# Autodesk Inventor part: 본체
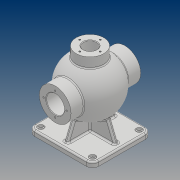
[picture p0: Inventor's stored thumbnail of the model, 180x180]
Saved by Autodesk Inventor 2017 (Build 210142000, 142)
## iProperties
Part Number: 본체
Material: 일반
Document SubType Name: Modeling
Designer: 13
Density: 1 g/cm^3
Appearance: 기본값
Author: 13
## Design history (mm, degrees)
sketch "스케치1"
  geometry: L1 (53, 0)-(-53, 0); A1 r 53 centre (0, 0) between (53, 0) and (-53, 0); 1 further point
  constraints: 2 end point, 2 horizontal alignment, 2 point on circle, 1 centre point, 1 coincident, 1 horizontal
  dimensions: "d1" = 53 radius of A1
revolve "회전1" sketch "스케치1" stored, may be unused: angle "d2" = 90 deg
sketch "스케치2"
  geometry: L1 (43, 0)-(-43, 0); L2 (0, 0)-(-100, 0); A1 r 43 centre (0, 0) between (43, 0) and (-43, 0); 1 further point
  constraints: 4 end point, 2 horizontal alignment, 2 point on circle, 1 centre point, 1 coincident, 1 horizontal, 1 midpoint, 1 point on line
  dimensions: "d3" = 43 radius of A1; "d4" = 100 distance of L2.start L2.end
revolve "회전2" sketch "스케치2" stored, may be unused: angle "d5" = 90 deg
node "작업 평면2"
sketch "스케치3"
  geometry: C1 r 31 at (0, 0); 1 further point
  constraints: 1 centre point, 1 coincident
  dimensions: "d8" = 62 diameter of C1
extrude "돌출1" join sketch "스케치3" stored distance "d9" = 10; taper "d10" = 0 deg
sketch "스케치4"
  geometry: C1 r 17.5 at (0, 0); 1 further point
  constraints: 1 centre point, 1 coincident
  dimensions: "d11" = 35 diameter of C1
extrude "돌출2" cut sketch "스케치4" stored distance "d12" = 10; taper "d13" = 0 deg
node "작업 평면3"
sketch "스케치5"
  geometry: C1 r 27 at (0, 0); 1 further point
  constraints: 1 centre point, 1 coincident
  dimensions: "d15" = 54 diameter of C1
extrude "돌출3" join sketch "스케치5" stored distance "d16" = 10; taper "d17" = 0 deg
sketch "스케치6"
  geometry: C1 r 13 at (0, 0); 1 further point
  constraints: 1 centre point, 1 coincident
  dimensions: "d18" = 26 diameter of C1
extrude "돌출4" cut sketch "스케치6" distance "d19" = 40; taper "d20" = 0 deg
node "작업 평면4"
sketch "스케치7"
  geometry: C1 r 18.5 at (0, 0); 1 further point
  constraints: 1 centre point, 1 coincident
  dimensions: "d22" = 37 diameter of C1
extrude "돌출5" cut sketch "스케치7" distance "d23" = 1.75; taper "d24" = 0 deg
node "작업 평면5"
sketch "스케치8"
  geometry: L1 (-62.5, 57.5)-(62.5, 57.5); L2 (62.5, 57.5)-(62.5, -57.5); L3 (62.5, -57.5)-(-62.5, -57.5); L4 (-62.5, -57.5)-(-62.5, 57.5); L5 (-62.5, 57.5)-(62.5, -57.5); L6 (62.5, 57.5)-(-62.5, -57.5); 1 further point
  constraints: 12 end point, 2 midpoint, 2 parallel, 1 horizontal, 1 perpendicular
  dimensions: "d26" = 115 distance of L1.end L2.end; "d27" = 125 distance of L1.start L1.end
extrude "돌출6" join sketch "스케치8" distance "d28" = 10; taper "d29" = 0 deg
sketch "스케치9"
  geometry: L1 (-4, 4)-(4, 4); L2 (4, 4)-(4, -4); L3 (4, -4)-(-4, -4); L4 (-4, -4)-(-4, 4); L5 (-4, 4)-(4, -4); L6 (4, 4)-(-4, -4); 1 further point
  constraints: 12 end point, 2 midpoint, 2 parallel, 1 horizontal, 1 perpendicular
  dimensions: "d30" = 8 distance of L2.end L3.end; "d31" = 8 distance of L1.end L2.end
extrude "돌출7" join sketch "스케치9" stored distance "d32" = 10; taper "d33" = 0 deg
sketch "스케치10"
  geometry: L1 (52.5, -75)-(39.167, -42); L2 (62.5, -85)-(62.5, -75) reference; L3 (-62.5, -75)-(62.5, -75) reference; 1 further point
  constraints: 2 end point, 1 point on line
  dimensions: "d34" = 10 distance from line of L1.start L2; "d36" = 22 deg angle of L2 L1; "d37" = 33 vertical distance of L1.start L1.end
feature "리브1" sketch "스케치10" dims "d38" = 1, "d39" = 8, "d40" = 0, "d41" = 0, "d42" = 1, "d43" = 1
sketch "스케치11"
  geometry: L1 (-52.5, -75)-(-42.399, -50); L2 (-62.5, -85)-(-62.5, -75) reference; L3 (62.5, -75)-(-62.5, -75) reference; 1 further point
  constraints: 2 end point, 1 point on line
  dimensions: "d44" = 10 distance from line of L2 L1.start; "d45" = 22 deg angle of L2 L1; "d46" = 25 vertical distance of L1.start L1.end
feature "리브2" sketch "스케치11" dims "d47" = 1, "d48" = 8, "d49" = 0, "d50" = 0, "d51" = 1, "d52" = 1
sketch "스케치12"
  geometry: L1 (-47.5, -75)-(-37.399, -50); L2 (-57.5, -85)-(-57.5, -75) reference; L3 (57.5, -75)-(-57.5, -75) reference; 1 further point
  constraints: 2 end point, 1 point on line
  dimensions: "d53" = 10 distance from line of L1.start L2; "d54" = 22 deg angle of L2 L1; "d55" = 25 vertical distance of L1.start L1.end
feature "리브3" sketch "스케치12" dims "d56" = 1, "d57" = 8, "d58" = 0, "d59" = 0, "d60" = 1, "d61" = 1
sketch "스케치13"
  geometry: L1 (47.5, -75)-(37.399, -50); L2 (57.5, -85)-(57.5, -75) reference; L3 (57.5, -75)-(-57.5, -75) reference; 1 further point
  constraints: 2 end point, 1 point on line
  dimensions: "d62" = 10 distance from line of L2 L1.start; "d63" = 22 deg angle of L2 L1; "d64" = 25 vertical distance of L1.start L1.end
feature "리브4" sketch "스케치13" dims "d65" = 1, "d66" = 8, "d67" = 0, "d68" = 0, "d69" = 1, "d70" = 1
fillet "모깎기1" dims "d71" = 12
sketch "스케치15"
  geometry: 2 further points
  constraints: 1 vertical alignment
  dimensions: "d75" = 22.5 distance of point (0, 0) point (0, 22.5)
hole "구멍1" sketch "스케치15" at (0, 22.5) diameter "d76" = 3.242; stored, may be unused: countersink angle "d80" = 90 deg, drill point angle "d82" = 118 deg; dims "d77" = 12, "d78" = 4, "d79" = 2, "d81" = 15
sketch "스케치16"
  geometry: 2 further points
  constraints: 1 vertical alignment
  dimensions: "d86" = 24 distance of point (0, -24) point (0, 0)
hole "구멍2" sketch "스케치16" at (0, -24) diameter "d87" = 3.242; stored, may be unused: countersink angle "d91" = 90 deg, drill point angle "d93" = 118 deg; dims "d88" = 16, "d89" = 4, "d90" = 2, "d92" = 19
sketch "스케치17"
  geometry: L1 (-4, -4)-(-4, -33.66) reference; 2 further points
  constraints: 1 vertical alignment
  dimensions: "d97" = 20 distance of point (0, -20) point (0, 0)
hole "구멍3" sketch "스케치17" at (0, -20) diameter "d98" = 3.242; stored, may be unused: countersink angle "d102" = 90 deg, drill point angle "d104" = 118 deg; dims "d99" = 9, "d100" = 4, "d101" = 2, "d103" = 11
chamfer "모따기1" distance "d108" = 1; stored, may be unused: second distance "d109" = 2, angle "d110" = 45 deg
sketch "스케치18"
  geometry: A1 r 12 centre (-50.5, 45.5) between (-50.5, 57.5) and (-62.5, 45.5) reference; A2 r 12 centre (50.5, 45.5) between (62.5, 45.5) and (50.5, 57.5) reference; A3 r 12 centre (50.5, -45.5) between (50.5, -57.5) and (62.5, -45.5) reference; A4 r 12 centre (-50.5, -45.5) between (-62.5, -45.5) and (-50.5, -57.5) reference; 5 further points
  constraints: 4 coincident
hole "구멍4" sketch "스케치18" at (-50.5, 45.5), (50.5, 45.5), (50.5, -45.5), (-50.5, -45.5) diameter "d111" = 8; stored, may be unused: countersink angle "d115" = 90 deg, drill point angle "d117" = 118 deg; dims "d112" = 9, "d113" = 12, "d114" = 3, "d116" = 11
fillet "모깎기2" dims "d118" = 3
fillet "모깎기3" dims "d119" = 3
node "작업 평면6"
sketch "스케치19"
  geometry: L1 (-27, 65)-(-27, 47.286) reference; L2 (-27, 65)-(27, 65) reference; 2 further points
  constraints: 1 other
  dimensions: "d121" = 27 distance from line of point (0, 55) L1; "d122" = 10 distance from line of point (0, 55) L2
feature "엠보싱1" sketch "스케치19" dims "d1" = 53, "d123" = 0.5, "d124" = 0
node "솔리드1"
mirror "미러1"
pattern_circular "원형 패턴1" dims angle "d84" = 360 deg
pattern_circular "원형 패턴2" dims angle "d95" = 360 deg
pattern_circular "원형 패턴3" dims angle "d106" = 360 deg
other parameters: "d7" = -68, "d14" = 65, "d21" = -16, "d25" = -85, "d120" = -65.75
